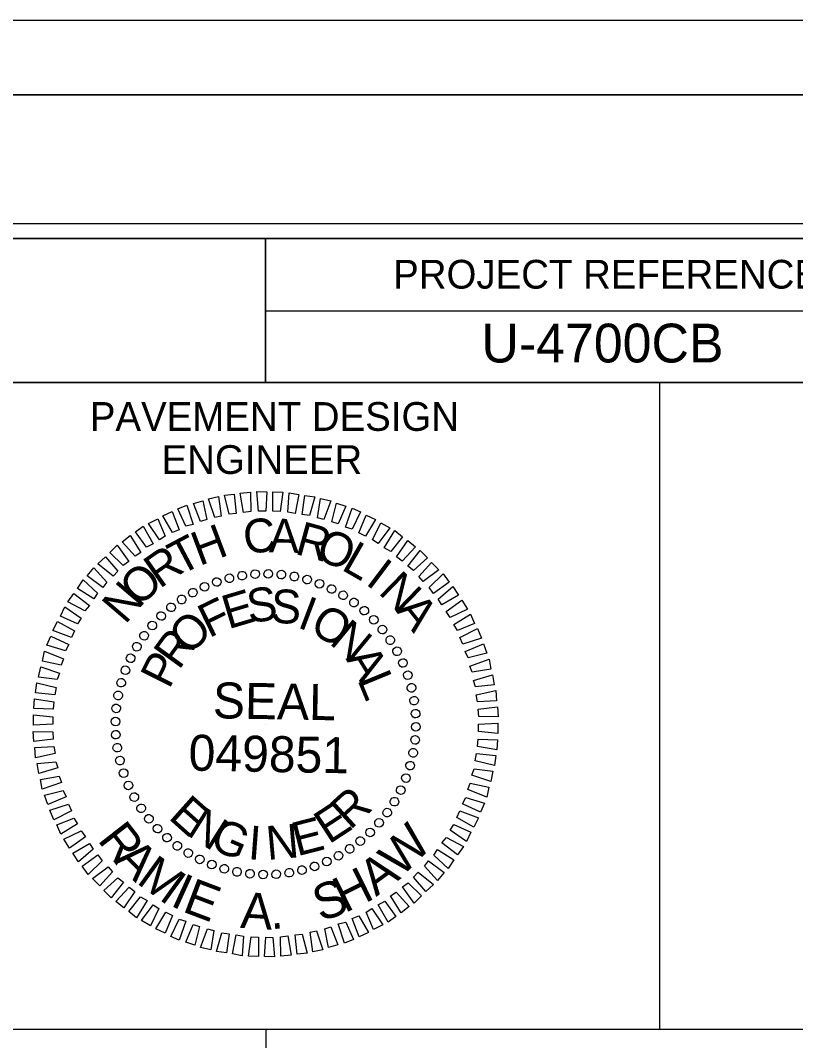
# Model space of a CAD drawing. Extents: x 2294455 to 2294795, y 719276 to 719941.
# Drawn here: x 2294739.38 to 2294766.36, y 719683.27 to 719718.76 of the extents above; entities that cross this region are included whole.
import ezdxf

# ---------------------------------------------------------------- set-up
doc = ezdxf.new("R2010")
doc.units = 0
for name, color, linetype in [('Default', 7, 'Continuous'), ('Old_Level_1', 7, 'Continuous'), ('Old_Level_2', 7, 'Continuous'), ('Sheet Data Field CELL', 7, 'Continuous'), ('Sheet Plan CELL', 7, 'Continuous'), ('Sheet Plot Border Inside CELL', 7, 'Continuous'), ('Sheet Plot Border Outside CELL', 7, 'Continuous'), ('Sheet Sticker Exception Certification CELL', 7, 'Continuous'), ('Sheet Typical CELL', 7, 'Continuous')]:
    doc.layers.add(name, color=color, linetype=linetype)

msp = doc.modelspace()

# ---------------------------------------------------------------- linework, layer by layer
at = {"layer": 'Default'}
msp.add_lwpolyline([(2294454.524, 719716.169), (2294794.524, 719716.169), (2294794.524, 719496.169), (2294454.524, 719496.169)], close=True, dxfattribs=at)
at = {"layer": 'Old_Level_1'}
msp.add_lwpolyline([(2294747.917, 719676.44), (2294787.924, 719676.44), (2294787.924, 719683.659), (2294747.917, 719683.659)], close=True, dxfattribs=at)
at = {"layer": 'Old_Level_2'}
for p, q in [((2294454.524, 719716.169), (2294794.524, 719716.169)), ((2294747.103, 719699.441), (2294747.103, 719699.441)), ((2294747.551, 719699.504), (2294747.551, 719699.504)), ((2294748.01, 719699.514), (2294748.01, 719699.514)), ((2294748.469, 719699.483), (2294748.469, 719699.483)), ((2294748.917, 719699.41), (2294748.917, 719699.41)), ((2294745.789, 719699.066), (2294745.789, 719699.066)), ((2294746.206, 719699.233), (2294746.206, 719699.233)), ((2294746.644, 719699.358), (2294746.644, 719699.358)), ((2294749.355, 719699.316), (2294749.355, 719699.316)), ((2294749.794, 719699.17), (2294749.794, 719699.17)), ((2294745.382, 719698.857), (2294745.382, 719698.857)), ((2294750.211, 719698.983), (2294750.211, 719698.983)), ((2294750.617, 719698.774), (2294750.617, 719698.774)), ((2294744.62, 719698.357), (2294744.62, 719698.357)), ((2294744.986, 719698.618), (2294744.986, 719698.618)), ((2294750.993, 719698.513), (2294750.993, 719698.513)), ((2294744.276, 719698.044), (2294744.276, 719698.044)), ((2294751.358, 719698.232), (2294751.358, 719698.232)), ((2294743.963, 719697.721), (2294743.963, 719697.721)), ((2294751.681, 719697.919), (2294751.681, 719697.919)), ((2294743.682, 719697.356), (2294743.682, 719697.356)), ((2294751.994, 719697.575), (2294751.994, 719697.575)), ((2294743.421, 719696.98), (2294743.421, 719696.98)), ((2294752.255, 719697.21), (2294752.255, 719697.21)), ((2294743.213, 719696.573), (2294743.213, 719696.573)), ((2294752.495, 719696.813), (2294752.495, 719696.813)), ((2294752.703, 719696.407), (2294752.703, 719696.407)), ((2294743.025, 719696.156), (2294743.025, 719696.156)), ((2294752.87, 719695.989), (2294752.87, 719695.989)), ((2294742.879, 719695.718), (2294742.879, 719695.718)), ((2294752.995, 719695.551), (2294752.995, 719695.551)), ((2294742.785, 719695.28), (2294742.785, 719695.28)), ((2294742.712, 719694.832), (2294742.712, 719694.832)), ((2294753.079, 719695.092), (2294753.079, 719695.092)), ((2294753.141, 719694.644), (2294753.141, 719694.644)), ((2294742.681, 719694.373), (2294742.681, 719694.373)), ((2294747.916, 719694.279), (2294747.916, 719694.279)), ((2294753.152, 719694.185), (2294753.152, 719694.185)), ((2294742.691, 719693.914), (2294742.691, 719693.914)), ((2294753.121, 719693.726), (2294753.121, 719693.726)), ((2294742.754, 719693.465), (2294742.754, 719693.465)), ((2294742.837, 719693.006), (2294742.837, 719693.006)), ((2294753.047, 719693.278), (2294753.047, 719693.278)), ((2294752.954, 719692.84), (2294752.954, 719692.84)), ((2294742.962, 719692.568), (2294742.962, 719692.568)), ((2294752.808, 719692.402), (2294752.808, 719692.402)), ((2294743.129, 719692.151), (2294743.129, 719692.151)), ((2294752.62, 719691.984), (2294752.62, 719691.984)), ((2294743.338, 719691.745), (2294743.338, 719691.745)), ((2294743.578, 719691.348), (2294743.578, 719691.348)), ((2294752.411, 719691.578), (2294752.411, 719691.578)), ((2294743.838, 719690.983), (2294743.838, 719690.983)), ((2294752.151, 719691.202), (2294752.151, 719691.202)), ((2294744.151, 719690.639), (2294744.151, 719690.639)), ((2294751.869, 719690.837), (2294751.869, 719690.837)), ((2294744.474, 719690.326), (2294744.474, 719690.326)), ((2294751.212, 719690.201), (2294751.212, 719690.201)), ((2294751.556, 719690.514), (2294751.556, 719690.514)), ((2294744.84, 719690.045), (2294744.84, 719690.045)), ((2294750.847, 719689.94), (2294750.847, 719689.94)), ((2294745.215, 719689.784), (2294745.215, 719689.784)), ((2294745.622, 719689.575), (2294745.622, 719689.575)), ((2294750.044, 719689.492), (2294750.044, 719689.492)), ((2294750.451, 719689.7), (2294750.451, 719689.7)), ((2294746.039, 719689.387), (2294746.039, 719689.387)), ((2294746.477, 719689.241), (2294746.477, 719689.241)), ((2294746.915, 719689.148), (2294746.915, 719689.148)), ((2294748.73, 719689.116), (2294748.73, 719689.116)), ((2294749.189, 719689.2), (2294749.189, 719689.2)), ((2294749.627, 719689.325), (2294749.627, 719689.325)), ((2294747.363, 719689.075), (2294747.363, 719689.075)), ((2294747.822, 719689.043), (2294747.822, 719689.043)), ((2294748.281, 719689.054), (2294748.281, 719689.054))]:
    msp.add_line(p, q, dxfattribs=at)
for points in [[(2294746.644, 719701.58), (2294746.477, 719702.247), (2294746.821, 719702.278), (2294746.894, 719701.611)], [(2294747.144, 719701.642), (2294747.03, 719702.31), (2294747.384, 719702.351), (2294747.395, 719701.673)], [(2294747.666, 719701.694), (2294747.614, 719702.372), (2294747.958, 719702.362), (2294747.916, 719701.684)], [(2294748.167, 719701.684), (2294748.167, 719702.362), (2294748.511, 719702.351), (2294748.417, 719701.673)], [(2294748.688, 719701.653), (2294748.73, 719702.33), (2294749.074, 719702.268), (2294748.938, 719701.611)], [(2294749.189, 719701.569), (2294749.282, 719702.237), (2294749.627, 719702.184), (2294749.439, 719701.538)], [(2294745.132, 719701.162), (2294744.86, 719701.767), (2294745.173, 719701.892), (2294745.392, 719701.225)], [(2294745.643, 719701.329), (2294745.403, 719701.955), (2294745.726, 719702.049), (2294745.862, 719701.402)], [(2294746.143, 719701.465), (2294745.924, 719702.122), (2294746.279, 719702.195), (2294746.362, 719701.517)], [(2294749.72, 719701.454), (2294749.825, 719702.132), (2294750.179, 719702.049), (2294749.94, 719701.402)], [(2294750.221, 719701.319), (2294750.378, 719701.965), (2294750.701, 719701.861), (2294750.44, 719701.246)], [(2294744.673, 719700.943), (2294744.339, 719701.527), (2294744.662, 719701.673), (2294744.902, 719701.037)], [(2294750.69, 719701.131), (2294750.93, 719701.788), (2294751.222, 719701.663), (2294750.93, 719701.058)], [(2294751.16, 719700.933), (2294751.42, 719701.548), (2294751.744, 719701.402), (2294751.389, 719700.818)], [(2294743.765, 719700.432), (2294743.379, 719700.964), (2294743.651, 719701.162), (2294743.995, 719700.557)], [(2294744.224, 719700.693), (2294743.838, 719701.256), (2294744.162, 719701.423), (2294744.422, 719700.818)], [(2294751.64, 719700.693), (2294751.921, 719701.287), (2294752.234, 719701.11), (2294751.838, 719700.568)], [(2294743.369, 719700.119), (2294742.92, 719700.62), (2294743.202, 719700.839), (2294743.567, 719700.255)], [(2294752.046, 719700.411), (2294752.411, 719701.016), (2294752.682, 719700.797), (2294752.276, 719700.286)], [(2294742.952, 719699.796), (2294742.493, 719700.255), (2294742.743, 719700.505), (2294743.15, 719699.942)], [(2294752.474, 719700.099), (2294752.86, 719700.672), (2294753.131, 719700.443), (2294752.672, 719699.953)], [(2294742.608, 719699.431), (2294742.076, 719699.859), (2294742.336, 719700.099), (2294742.774, 719699.598)], [(2294752.87, 719699.775), (2294753.298, 719700.318), (2294753.548, 719700.067), (2294753.068, 719699.619)], [(2294753.246, 719699.41), (2294753.694, 719699.9), (2294753.944, 719699.65), (2294753.402, 719699.243)], [(2294742.243, 719699.035), (2294741.7, 719699.441), (2294741.93, 719699.713), (2294742.389, 719699.222)], [(2294753.611, 719699.035), (2294754.09, 719699.504), (2294754.309, 719699.222), (2294753.757, 719698.826)], [(2294741.93, 719698.638), (2294741.366, 719698.993), (2294741.565, 719699.295), (2294742.065, 719698.837)], [(2294753.924, 719698.628), (2294754.435, 719699.066), (2294754.633, 719698.764), (2294754.049, 719698.43)], [(2294741.617, 719698.221), (2294741.033, 719698.534), (2294741.241, 719698.826), (2294741.784, 719698.409)], [(2294741.366, 719697.773), (2294740.772, 719698.033), (2294740.928, 719698.357), (2294741.492, 719697.971)], [(2294754.195, 719698.2), (2294754.747, 719698.597), (2294754.946, 719698.284), (2294754.341, 719697.992)], [(2294754.466, 719697.741), (2294755.05, 719698.107), (2294755.186, 719697.783), (2294754.591, 719697.543)], [(2294741.158, 719697.293), (2294740.511, 719697.533), (2294740.668, 719697.856), (2294741.262, 719697.522)], [(2294740.949, 719696.834), (2294740.303, 719697.022), (2294740.438, 719697.345), (2294741.064, 719697.053)], [(2294754.674, 719697.293), (2294755.29, 719697.606), (2294755.425, 719697.272), (2294754.779, 719697.064)], [(2294754.862, 719696.803), (2294755.498, 719697.074), (2294755.613, 719696.751), (2294754.967, 719696.584)], [(2294740.793, 719696.333), (2294740.146, 719696.469), (2294740.219, 719696.813), (2294740.876, 719696.553)], [(2294740.657, 719695.833), (2294740.011, 719695.916), (2294740.084, 719696.271), (2294740.741, 719696.052)], [(2294755.029, 719696.302), (2294755.697, 719696.542), (2294755.759, 719696.198), (2294755.102, 719696.083)], [(2294755.154, 719695.802), (2294755.811, 719696), (2294755.874, 719695.645), (2294755.217, 719695.583)], [(2294740.574, 719695.301), (2294739.906, 719695.364), (2294739.948, 719695.718), (2294740.626, 719695.551)], [(2294740.522, 719694.8), (2294739.844, 719694.821), (2294739.865, 719695.165), (2294740.543, 719695.051)], [(2294755.248, 719695.301), (2294755.926, 719695.447), (2294755.957, 719695.092), (2294755.29, 719695.051)], [(2294755.311, 719694.8), (2294755.989, 719694.884), (2294756.009, 719694.529), (2294755.332, 719694.55)], [(2294740.511, 719694.279), (2294739.833, 719694.248), (2294739.833, 719694.602), (2294740.511, 719694.529)], [(2294755.321, 719694.279), (2294755.999, 719694.31), (2294755.999, 719693.956), (2294755.321, 719694.029)], [(2294740.522, 719693.757), (2294739.844, 719693.674), (2294739.823, 719694.029), (2294740.501, 719694.008)], [(2294755.311, 719693.757), (2294755.989, 719693.737), (2294755.968, 719693.392), (2294755.29, 719693.507)], [(2294740.584, 719693.257), (2294739.906, 719693.111), (2294739.875, 719693.465), (2294740.543, 719693.507)], [(2294755.259, 719693.257), (2294755.926, 719693.194), (2294755.884, 719692.84), (2294755.206, 719693.006)], [(2294740.678, 719692.756), (2294740.021, 719692.558), (2294739.959, 719692.913), (2294740.616, 719692.975)], [(2294755.175, 719692.725), (2294755.822, 719692.641), (2294755.749, 719692.287), (2294755.092, 719692.506)], [(2294740.803, 719692.256), (2294740.136, 719692.016), (2294740.073, 719692.36), (2294740.73, 719692.475)], [(2294740.97, 719691.755), (2294740.334, 719691.484), (2294740.219, 719691.807), (2294740.866, 719691.974)], [(2294755.04, 719692.224), (2294755.686, 719692.089), (2294755.613, 719691.745), (2294754.956, 719692.005)], [(2294754.883, 719691.724), (2294755.53, 719691.536), (2294755.394, 719691.213), (2294754.768, 719691.505)], [(2294741.158, 719691.265), (2294740.543, 719690.952), (2294740.407, 719691.286), (2294741.054, 719691.494)], [(2294754.674, 719691.265), (2294755.321, 719691.025), (2294755.165, 719690.702), (2294754.57, 719691.035)], [(2294741.366, 719690.816), (2294740.782, 719690.451), (2294740.647, 719690.775), (2294741.241, 719691.014)], [(2294741.638, 719690.357), (2294741.085, 719689.961), (2294740.887, 719690.274), (2294741.492, 719690.566)], [(2294754.466, 719690.785), (2294755.06, 719690.524), (2294754.904, 719690.201), (2294754.341, 719690.587)], [(2294754.216, 719690.337), (2294754.8, 719690.024), (2294754.591, 719689.732), (2294754.049, 719690.149)], [(2294741.909, 719689.93), (2294741.398, 719689.492), (2294741.2, 719689.794), (2294741.784, 719690.128)], [(2294753.903, 719689.919), (2294754.466, 719689.565), (2294754.268, 719689.262), (2294753.767, 719689.721)], [(2294742.222, 719689.523), (2294741.742, 719689.054), (2294741.523, 719689.335), (2294742.076, 719689.732)], [(2294753.59, 719689.523), (2294754.132, 719689.116), (2294753.903, 719688.845), (2294753.444, 719689.335)], [(2294742.587, 719689.148), (2294742.138, 719688.657), (2294741.888, 719688.908), (2294742.43, 719689.314)], [(2294753.225, 719689.127), (2294753.757, 719688.699), (2294753.496, 719688.459), (2294753.058, 719688.96)], [(2294742.962, 719688.783), (2294742.535, 719688.24), (2294742.284, 719688.491), (2294742.764, 719688.939)], [(2294752.881, 719688.762), (2294753.34, 719688.303), (2294753.089, 719688.052), (2294752.682, 719688.616)], [(2294743.359, 719688.459), (2294742.973, 719687.886), (2294742.701, 719688.115), (2294743.16, 719688.605)], [(2294752.463, 719688.438), (2294752.912, 719687.938), (2294752.63, 719687.719), (2294752.265, 719688.303)], [(2294743.786, 719688.146), (2294743.421, 719687.541), (2294743.15, 719687.76), (2294743.557, 719688.272)], [(2294752.067, 719688.126), (2294752.453, 719687.594), (2294752.182, 719687.395), (2294751.838, 719688)], [(2294744.193, 719687.865), (2294743.911, 719687.27), (2294743.598, 719687.448), (2294743.995, 719687.99)], [(2294744.673, 719687.625), (2294744.412, 719687.01), (2294744.089, 719687.156), (2294744.443, 719687.74)], [(2294751.608, 719687.865), (2294751.994, 719687.302), (2294751.671, 719687.135), (2294751.41, 719687.74)], [(2294745.142, 719687.427), (2294744.902, 719686.77), (2294744.61, 719686.895), (2294744.902, 719687.5)], [(2294750.701, 719687.395), (2294750.972, 719686.791), (2294750.659, 719686.665), (2294750.44, 719687.333)], [(2294751.16, 719687.614), (2294751.494, 719687.03), (2294751.17, 719686.884), (2294750.93, 719687.521)], [(2294745.611, 719687.239), (2294745.455, 719686.592), (2294745.132, 719686.697), (2294745.392, 719687.312)], [(2294746.112, 719687.103), (2294746.008, 719686.425), (2294745.653, 719686.509), (2294745.893, 719687.156)], [(2294746.644, 719686.989), (2294746.55, 719686.321), (2294746.206, 719686.373), (2294746.393, 719687.02)], [(2294749.189, 719686.978), (2294749.355, 719686.311), (2294749.011, 719686.279), (2294748.938, 719686.947)], [(2294749.689, 719687.093), (2294749.908, 719686.436), (2294749.554, 719686.363), (2294749.47, 719687.041)], [(2294750.19, 719687.229), (2294750.43, 719686.603), (2294750.106, 719686.509), (2294749.971, 719687.156)], [(2294747.144, 719686.905), (2294747.103, 719686.227), (2294746.759, 719686.29), (2294746.894, 719686.947)], [(2294747.666, 719686.874), (2294747.666, 719686.196), (2294747.322, 719686.206), (2294747.416, 719686.884)], [(2294748.167, 719686.864), (2294748.219, 719686.186), (2294747.874, 719686.196), (2294747.916, 719686.874)], [(2294748.688, 719686.916), (2294748.803, 719686.248), (2294748.448, 719686.206), (2294748.438, 719686.884)]]:
    msp.add_lwpolyline(points, close=True, dxfattribs=at)
for centre, major_axis in [((2294746.213, 719699.225), (-0.049, 0.142)), ((2294746.651, 719699.355), (-0.036, 0.146)), ((2294747.098, 719699.446), (-0.023, 0.148)), ((2294747.551, 719699.498), (-0.01, 0.15)), ((2294748.007, 719699.51), (0.003, 0.15)), ((2294748.463, 719699.482), (0.016, 0.149)), ((2294748.914, 719699.414), (0.029, 0.147)), ((2294749.358, 719699.308), (0.041, 0.144)), ((2294745.788, 719699.058), (-0.061, 0.137)), ((2294749.791, 719699.163), (0.054, 0.14)), ((2294750.21, 719698.981), (0.066, 0.135)), ((2294744.991, 719698.616), (-0.084, 0.125)), ((2294745.38, 719698.854), (-0.073, 0.131)), ((2294750.611, 719698.763), (0.077, 0.129)), ((2294750.991, 719698.511), (0.088, 0.122)), ((2294744.624, 719698.344), (-0.095, 0.117)), ((2294751.348, 719698.227), (0.099, 0.113)), ((2294744.282, 719698.042), (-0.104, 0.108)), ((2294751.679, 719697.913), (0.108, 0.104)), ((2294743.968, 719697.711), (-0.113, 0.099)), ((2294751.982, 719697.571), (0.117, 0.095)), ((2294743.684, 719697.354), (-0.122, 0.088)), ((2294752.253, 719697.204), (0.125, 0.084)), ((2294743.432, 719696.973), (-0.129, 0.077)), ((2294752.492, 719696.815), (0.131, 0.073)), ((2294743.214, 719696.572), (-0.135, 0.066)), ((2294752.695, 719696.407), (0.137, 0.061)), ((2294743.032, 719696.154), (-0.14, 0.054)), ((2294742.887, 719695.721), (-0.144, 0.041)), ((2294752.863, 719695.982), (0.142, 0.049)), ((2294752.992, 719695.544), (0.146, 0.036)), ((2294742.781, 719695.277), (-0.147, 0.029)), ((2294753.083, 719695.097), (0.148, 0.023)), ((2294742.713, 719694.826), (-0.149, 0.016)), ((2294753.135, 719694.644), (0.15, 0.01)), ((2294742.686, 719694.37), (-0.15, 0.003)), ((2294742.698, 719693.914), (-0.15, -0.01)), ((2294753.147, 719694.188), (0.15, -0.003)), ((2294753.119, 719693.732), (0.149, -0.016)), ((2294742.749, 719693.461), (-0.148, -0.023)), ((2294753.052, 719693.281), (0.147, -0.029)), ((2294742.84, 719693.013), (-0.146, -0.036)), ((2294752.945, 719692.837), (0.144, -0.041)), ((2294742.97, 719692.576), (-0.142, -0.049)), ((2294743.137, 719692.151), (-0.137, -0.061)), ((2294752.8, 719692.404), (0.14, -0.054)), ((2294752.618, 719691.986), (0.135, -0.066)), ((2294743.341, 719691.743), (-0.131, -0.073)), ((2294752.4, 719691.585), (0.129, -0.077)), ((2294743.579, 719691.354), (-0.125, -0.084)), ((2294752.149, 719691.204), (0.122, -0.088)), ((2294743.851, 719690.987), (-0.117, -0.095)), ((2294751.864, 719690.847), (0.113, -0.099)), ((2294744.153, 719690.645), (-0.108, -0.104)), ((2294751.55, 719690.516), (0.104, -0.108)), ((2294744.484, 719690.331), (-0.099, -0.113)), ((2294744.841, 719690.047), (-0.088, -0.122)), ((2294751.208, 719690.213), (0.095, -0.117)), ((2294745.222, 719689.795), (-0.077, -0.129)), ((2294750.452, 719689.703), (0.073, -0.131)), ((2294750.842, 719689.942), (0.084, -0.125)), ((2294745.623, 719689.577), (-0.066, -0.135)), ((2294746.041, 719689.395), (-0.054, -0.14)), ((2294749.619, 719689.332), (0.049, -0.142)), ((2294750.044, 719689.5), (0.061, -0.137)), ((2294746.474, 719689.25), (-0.041, -0.144)), ((2294746.918, 719689.144), (-0.029, -0.147)), ((2294747.369, 719689.076), (-0.016, -0.149)), ((2294747.825, 719689.048), (-0.003, -0.15)), ((2294748.281, 719689.06), (0.01, -0.15)), ((2294748.735, 719689.112), (0.023, -0.148)), ((2294749.182, 719689.203), (0.036, -0.146))]:
    msp.add_ellipse(centre, major_axis=major_axis, ratio=0.999708, dxfattribs=at)
at = {"layer": 'Sheet Plan CELL'}
for points in [[(2294761.64, 719683.659), (2294735.355, 719683.659), (2294735.355, 719706.159), (2294761.64, 719706.159)], [(2294787.924, 719683.659), (2294761.64, 719683.659), (2294761.64, 719706.159), (2294787.924, 719706.159)]]:
    msp.add_lwpolyline(points, dxfattribs=at)
at = {"layer": 'Sheet Plot Border Inside CELL'}
msp.add_lwpolyline([(2294790.424, 719711.679), (2294457.124, 719711.679), (2294457.124, 719500.659), (2294790.424, 719500.659)], close=True, dxfattribs=at)
at = {"layer": 'Sheet Plot Border Outside CELL'}
for points in [[(2294793.79, 719718.758), (2294456.99, 719718.758), (2294456.99, 719498.758), (2294793.79, 719498.758)], [(2294454.524, 719496.169), (2294791.324, 719496.169), (2294791.324, 719716.169), (2294454.524, 719716.169)], [(2294794.524, 719716.169), (2294454.524, 719716.169), (2294454.524, 719496.169), (2294794.524, 719496.169)]]:
    msp.add_lwpolyline(points, close=True, dxfattribs=at)
at = {"layer": 'Sheet Sticker Exception Certification CELL'}
for p, q in [((2294705.291, 719711.172), (2294747.914, 719711.172)), ((2294747.914, 719711.169), (2294747.914, 719706.162)), ((2294747.914, 719706.165), (2294705.291, 719706.165))]:
    msp.add_line(p, q, dxfattribs=at)
at = {"layer": 'Sheet Typical CELL'}
msp.add_line((2294747.914, 719708.659), (2294787.924, 719708.659), dxfattribs=at)
for points in [[(2294787.924, 719711.169), (2294487.924, 719711.169), (2294487.924, 719501.169), (2294787.924, 719501.169)], [(2294747.914, 719711.169), (2294787.924, 719711.169), (2294787.924, 719706.159), (2294747.914, 719706.159)]]:
    msp.add_lwpolyline(points, close=True, dxfattribs=at)

# ---------------------------------------------------------------- texts
at = {"layer": 'Default'}
for s, rotation, p in [('R', 308.005, (2294742.036, 719690.247)), ('W', 45.0672, (2294752.625, 719688.918)), ('A', 315.3996, (2294742.602, 719689.523)), ('M', 324.1387, (2294743.383, 719688.771)), ('A', 36.3281, (2294751.758, 719688.265)), ('H', 26.4584, (2294750.673, 719687.695)), ('I', 335.5363, (2294744.558, 719687.983)), ('E', 339.2947, (2294744.976, 719687.776)), ('S', 19.2166, (2294749.824, 719687.4)), ('A', 356.4062, (2294747.015, 719687.198)), ('.', 5.1454, (2294748.098, 719687.143))]:
    msp.add_text(s, height=1.251, rotation=rotation, dxfattribs=at).set_placement(p)
at = {"layer": 'Old_Level_2'}
for s, height, rotation, p in [('H', 1.176, 20.6195, (2294745.611, 719699.775)), ('C', 1.176, 6.2199, (2294747.197, 719700.192)), ('A', 1.176, 359.0203, (2294748.02, 719700.255)), ('R', 1.176, 344.6211, (2294748.897, 719700.213)), ('T', 1.176, 27.8198, (2294744.933, 719699.431)), ('O', 1.176, 337.4212, (2294749.595, 719700.057)), ('L', 1.176, 330.2209, (2294750.513, 719699.671)), ('R', 1.176, 35.0205, (2294744.224, 719698.972)), ('O', 1.176, 42.2217, (2294743.505, 719698.326)), ('I', 1.176, 323.0201, (2294751.358, 719699.17)), ('N', 1.176, 315.8189, (2294751.806, 719698.847)), ('N', 1.176, 49.4235, (2294743.025, 719697.721)), ('S', 1.176, 7.2556, (2294747.332, 719697.794)), ('F', 1.176, 25.967, (2294745.945, 719697.262)), ('E', 1.176, 16.6111, (2294746.613, 719697.575)), ('S', 1.176, 357.9004, (2294748.083, 719697.804)), ('I', 1.176, 339.1896, (2294748.98, 719697.658)), ('O', 1.176, 329.8335, (2294749.397, 719697.512)), ('A', 1.176, 308.6172, (2294752.422, 719698.232)), ('O', 1.176, 44.6812, (2294745.257, 719696.646)), ('N', 1.176, 320.4766, (2294750.096, 719697.095)), ('R', 1.176, 54.0397, (2294744.892, 719696.135)), ('P', 1.176, 63.3989, (2294744.558, 719695.468)), ('A', 1.176, 301.7603, (2294750.69, 719696.553)), ('L', 1.176, 292.4009, (2294751.097, 719695.833)), ('SEAL', 1.2512, 359, (2294746.07, 719694.487)), ('049851', 1.2515, 359, (2294745.225, 719692.666)), ('R', 1.176, 42.4814, (2294750.857, 719690.576)), ('E', 1.176, 318.2769, (2294744.495, 719691.014)), ('E', 1.176, 33.1241, (2294750.117, 719690.086)), ('N', 1.176, 327.634, (2294745.121, 719690.451)), ('G', 1.176, 336.9902, (2294745.914, 719689.982)), ('E', 1.176, 14.4118, (2294749.011, 719689.679)), ('I', 1.176, 355.7012, (2294747.28, 719689.586)), ('N', 1.176, 5.0564, (2294747.979, 719689.554))]:
    msp.add_text(s, height=height, rotation=rotation, dxfattribs=at).set_placement(p)
at = {"layer": 'Sheet Data Field CELL'}
msp.add_text('U-4700CB', height=1.35, dxfattribs=at).set_placement((2294755.427, 719706.86))
at = {"layer": 'Sheet Plan CELL'}
for s, height, p in [('PAVEMENT DESIGN', 1.00002, (2294741.794, 719704.482)), ('ENGINEER', 1, (2294744.291, 719702.983))]:
    msp.add_text(s, height=height, dxfattribs=at).set_placement(p)
at = {"layer": 'Sheet Typical CELL'}
msp.add_text('PROJECT REFERENCE NO.', height=1.00002, dxfattribs=at).set_placement((2294752.354, 719709.429))

doc.saveas('drawing.dxf')
